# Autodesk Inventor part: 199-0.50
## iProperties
Created: 2007-06
Part Number: 199-0.50
Document SubType Name: Modeling
Designer: btaylor
Density: 1 g/cm^3
Author: btaylor
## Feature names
1. Extrusion1
2. Extrusion2
3. Sweep1
4. Extrusion3
5. Extrusion4
6. Extrusion5
7. Fillet1
8. Fillet2
9. Fillet3
10. Fillet4
11. Extrusion6
12. Extrusion7
13. Extrusion8
14. Extrusion9
15. Sweep2
16. Chamfer1
17. Chamfer2
18. Chamfer3
19. Fillet5
20. Fillet6
21. Fillet7
22. Fillet8
23. Fillet9
24. Fillet10
25. Fillet11
